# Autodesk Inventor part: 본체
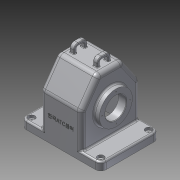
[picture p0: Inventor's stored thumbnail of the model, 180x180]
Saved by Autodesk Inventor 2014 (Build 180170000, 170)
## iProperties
Created: 2016-12
Part Number: 본체
Material: 알루미늄 6061
Document SubType Name: Modeling
Designer: USER
Density: 2.71 g/cm^3
Appearance: 알루미늄 - 평지
Mass: 1066.82 g
Surface Area: 1137.8 cm^2
Volume: 393.66 cm^3
Author: USER
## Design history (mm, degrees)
sketch "스케치1"
  geometry: L1 (0, 0)-(0, 139.451); L2 (0, 0)-(117.62, 0); L3 (0, 125)-(23.491, 125); L4 (23.491, 125)-(55, 80); L5 (55, 80)-(55, 0); L6 (55, 0)-(0, 0); L7 (0, 125)-(0, 0); L8 (0, 125)-(-23.491, 125); L9 (-23.491, 125)-(-55, 80); L10 (-55, 80)-(-55, 0); L11 (-55, 0)-(0, 0)
  constraints: 22 end point, 4 perpendicular, 3 symmetric about line, 2 point on line, 1 parallel, 1 vertical
  dimensions: "d0" = 80 distance of L4.end L5.end; "d1" = 35 deg angle of L4 L5; "d2" = 125 distance from line of L3 L5.end; "d3" = 110 diameter of L5 L1
extrude "돌출1" new body sketch "스케치1" stored distance "d4" = 77; taper "d5" = 0 deg
sketch "스케치2"
  geometry: L1 (55, 75)-(-55, 75); L2 (-55, 75)-(-55, -75); L3 (-55, -75)-(55, -75); L4 (55, -75)-(55, 75); L5 (0, 0)-(0, -86.258); L6 (0, 0)-(77.282, 0)
  constraints: 12 end point, 3 parallel, 2 perpendicular, 1 horizontal
  dimensions: "d6" = 150 diameter of L3 L6; "d7" = 110 diameter of L4 L5; "d8" = 110 distance between parallel lines of L4 L2; "d9" = 150 distance between parallel lines of L3 L1
extrude "돌출2" join sketch "스케치2" distance "d10" = 15; taper "d11" = 0 deg
sketch "스케치3"
  geometry: L1 (96, -38.5)-(65, -38.5); L2 (65, -38.5)-(65, -48.5); L3 (65, -48.5)-(96, -48.5); L4 (96, -48.5)-(96, -38.5); L5 (102.5, 43.5)-(65, 43.5); L6 (65, 43.5)-(65, 38.5); L7 (65, 38.5)-(102.5, 38.5); L8 (102.5, 38.5)-(102.5, 43.5); L9 (0, 0)-(165.185, 0); L10 (125, 38.5)-(80, 38.5) reference; L11 (80, -38.5)-(125, -38.5) reference; L12 (65, 46.962)-(65, -81.692); L13 (0, -75)-(0, 75) reference
  constraints: 20 end point, 4 parallel, 4 perpendicular, 3 point on line, 2 horizontal, 1 midpoint
  dimensions: "d12" = 5 distance between parallel lines of L5 L10; "d13" = 65 distance between parallel lines of L12 L13; "d14" = 62 diameter of L4 L12; "d15" = 87 distance between parallel lines of L3 L10; "d16" = 75 diameter of L8 L12
revolve "회전1" stored, may be unused: angle "d17" = 90 deg
revolve "회전2" stored, may be unused: angle "d18" = 90 deg
node "작업 평면1"
sketch "스케치4"
  geometry: L1 (55, 0)-(-55, 0) reference; L2 (-23.491, 125)-(23.491, 125) reference; L3 (0, 125)-(0, 155.963); L4 (12.5, 125)-(12.5, 132); L5 (7.5, 125)-(7.5, 132); L6 (-12.5, 125)-(-12.5, 132); L7 (-7.5, 125)-(-7.5, 132); L8 (-12.5, 125)-(-7.5, 125); L9 (7.5, 125)-(12.5, 125); L10 (4.5, 135)-(-4.5, 135); L11 (4.5, 140)-(-4.5, 140); A1 r 8 centre (4.5, 132) between (12.5, 132) and (4.5, 140); A2 r 8 centre (-4.5, 132) between (-4.5, 140) and (-12.5, 132); A3 r 3 centre (4.5, 132) between (7.5, 132) and (4.5, 135); A4 r 3 centre (-4.5, 132) between (-4.5, 135) and (-7.5, 132); 3 further points
  constraints: 18 end point, 8 point on circle, 6 symmetric about line, 5 tangent, 4 centre point, 4 parallel, 2 coincident, 2 collinear, 1 midpoint, 1 perpendicular, 1 point on line, 1 other
  dimensions: "d20" = 8 radius of A1; "d22" = 15 diameter of L5 L3; "d23" = 25 diameter of L4 L3; "d85" = 5 distance between parallel lines of L11 L10; "d86" = 140 distance between parallel lines of L1 L11
sketch "스케치5"
  geometry: L1 (27.5, 43.5)-(102.5, 43.5) reference; L2 (34, -48.5)-(96, -48.5) reference; L3 (65, 43.5)-(65, -48.5); L4 (65, 43.5)-(85, 43.5); L5 (85, 43.5)-(85, -48.5); L6 (85, -48.5)-(65, -48.5); L7 (65, -48.5)-(65, 43.5); 1 further point
  constraints: 10 end point, 2 midpoint, 2 parallel, 1 horizontal, 1 perpendicular, 1 point on line
  dimensions: "d28" = 40 diameter of L5 L3
revolve "회전3" sketch "스케치5" stored, may be unused: angle "d29" = 90 deg
sketch "스케치6"
  geometry: 1 further point
sketch "스케치7"
  geometry: L1 (55, 15)-(-55, 15) reference; L2 (-55, 15)-(-55, 80) reference; L3 (-55, 80)-(-23.491, 125) reference; L4 (-23.491, 125)-(23.491, 125) reference; L5 (23.491, 125)-(55, 80) reference; L6 (55, 80)-(55, 15) reference; L7 (50, 78.424)-(20.888, 120); L8 (20.888, 120)-(-20.888, 120); L9 (-20.888, 120)-(-50, 78.424); L10 (-50, 78.424)-(-50, 0); L11 (50, 0)-(50, 78.424); L12 (55, 0)-(-55, 0) reference; L13 (-50, 0)-(50, 0); C1 r 31 at (0, 65) reference; 1 further point
  constraints: 12 end point, 2 point on line, 1 collinear, 1 perpendicular, 3 other
  dimensions: "d30" = 5 distance between parallel lines of L3 L9; "d31" = 5 distance between parallel lines of L6 L11
extrude "돌출4" cut sketch "스케치7" stored distance "d32" = 67; taper "d33" = 0 deg
sketch "스케치10"
  geometry: 1 further point
sketch "스케치11"
  geometry: C1 r 31 at (0, 65) reference; C2 r 31 at (0, 65); 1 further point
  constraints: 1 centre point, 1 coincident, 1 concentric
extrude "돌출5" cut sketch "스케치11" stored distance "d34" = 10; taper "d35" = 0 deg
sketch "스케치12"
  geometry: L1 (45, 43.5)-(85, 43.5) reference; L2 (85, -48.5)-(45, -48.5) reference; L3 (65, 43.5)-(65, -48.5); L4 (85, 33.5)-(85, 43.5) reference; L5 (85, 33.5)-(106, 33.5); L6 (106, 33.5)-(92, 19.5); L7 (92, 19.5)-(85, 19.5); L8 (85, 19.5)-(85, 33.5); 1 further point
  constraints: 10 end point, 2 midpoint, 2 perpendicular, 1 parallel
  dimensions: "d36" = 54 diameter of L6.end L3; "d37" = 45 deg angle of L7 L6; "d38" = 24 distance between parallel lines of L7 L1
revolve "회전4" sketch "스케치12" stored, may be unused: angle "d39" = 90 deg
fillet "모깎기1" dims "d46" = 10
sketch "스케치14"
  geometry: L1 (45, 75)-(-45, 75) reference; L2 (55, 65)-(55, -65) reference; L3 (-45, -75)-(45, -75) reference; L4 (-55, 65)-(-55, -65) reference; L5 (50, 33.5)-(-50, 33.5) reference; L6 (-50, 33.5)-(-50, -33.5) reference; L7 (-50, -33.5)-(50, -33.5) reference; L8 (50, -33.5)-(50, 33.5) reference; A1 r 10 centre (-45, 65) between (-45, 75) and (-55, 65) reference; A2 r 10 centre (45, 65) between (55, 65) and (45, 75) reference; A3 r 10 centre (45, -65) between (45, -75) and (55, -65) reference; A4 r 10 centre (-45, -65) between (-55, -65) and (-45, -75) reference; 5 further points
  constraints: 4 coincident
hole "구멍1" sketch "스케치14" at (-45, -65), (45, -65), (45, 65), (-45, 65) diameter "d47" = 5; stored, may be unused: countersink angle "d51" = 90 deg, drill point angle "d53" = 118 deg; dims "d48" = 6, "d49" = 12, "d50" = 5, "d52" = 8
sketch "스케치15" dims "d54" = 52
  geometry: L1 (0, 0)-(0, 42.256); C1 r 31 at (0, 0) reference; 2 further points
  constraints: 2 end point, 1 coincident, 1 point on line, 1 vertical, 1 vertical alignment, 2 other
hole "구멍2" sketch "스케치15" at (0, 26) diameter "d55" = 2.459; stored, may be unused: countersink angle "d59" = 90 deg, drill point angle "d61" = 118 deg; dims "d56" = 6, "d57" = 12, "d58" = 5, "d60" = 8
sketch "스케치16" dims "d65" = 58
  geometry: L1 (0, 0)-(0, 34.84); C1 r 37.5 at (0, 0) reference; 2 further points
  constraints: 2 end point, 1 coincident, 1 point on line, 1 vertical, 1 vertical alignment, 2 other
hole "구멍3" sketch "스케치16" at (0, 29) diameter "d66" = 2.459; stored, may be unused: countersink angle "d70" = 90 deg, drill point angle "d72" = 118 deg; dims "d67" = 6, "d68" = 12, "d69" = 5, "d71" = 8
fillet "모깎기2" dims "d76" = 10
fillet "모깎기3" dims "d77" = 8
fillet "모깎기4" dims "d78" = 3
fillet "모깎기5" dims "d79" = 3
chamfer "모따기1" distance "d80" = 1; stored, may be unused: second distance "d81" = 2, angle "d82" = 45 deg
extrude "돌출6" join sketch "스케치4" distance "d87" = 8; taper "d88" = 0 deg
chamfer "모따기2" distance "d89" = 1; stored, may be unused: second distance "d90" = 2, angle "d91" = 45 deg
fillet "모깎기6" dims "d92" = 1
fillet "모깎기7" dims "d93" = 3
sketch "스케치18"
  geometry: L1 (18, 38.5)-(76.847, 38.5) reference; L2 (18, 0)-(76.847, 0); 2 further points
  constraints: 2 end point, 1 parallel, 1 point on line, 1 other
  dimensions: "d95" = 38.5 distance between parallel lines of L1 L2; "d96" = 45 distance of point (45, 0) point (0, 0)
feature "엠보싱1" sketch "스케치18" dims "d97" = 0.5, "d98" = 0
node "솔리드1"
pattern_circular "원형 패턴1" dims angle "d63" = 360 deg
pattern_circular "원형 패턴2" dims angle "d74" = 360 deg
mirror "대칭2"
mirror "대칭3"
node "투영된 루프1"
node "투영된 루프3"
other parameters: "d19" = -18, "d21" = 15
